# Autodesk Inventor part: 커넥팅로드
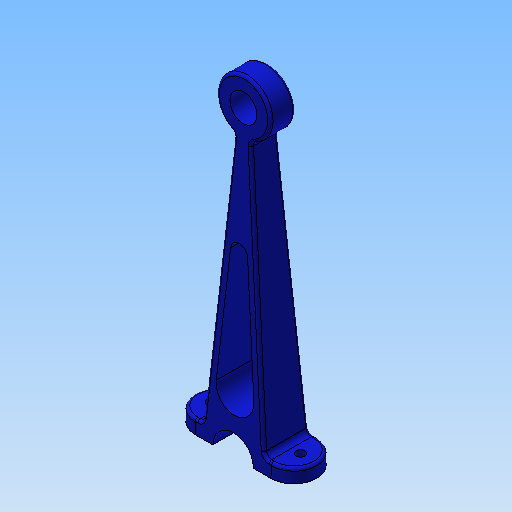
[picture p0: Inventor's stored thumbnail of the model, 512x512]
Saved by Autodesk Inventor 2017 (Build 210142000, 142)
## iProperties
Created: 2017-05
Part Number: 커넥팅로드
Material: 강철, 탄소
Document SubType Name: Modeling
Designer: mduedu
Density: 7.87 g/cm^3
Mass: 120.511 g
Surface Area: 85.3888 cm^2
Volume: 15.3127 cm^3
Appearance: 파란색 - 벽 페인트 - 무광
Author: mduedu
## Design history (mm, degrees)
sketch "스케치1"
  geometry: L1 (-22.5, 0)-(22.5, 0); L2 (22.5, 0)-(22.5, 5); L3 (-22.5, 5)-(-22.5, 0); L4 (-11.352, 5)-(-3, 100.461); L5 (0, 110)-(0, 0); L6 (11.352, 5)-(3, 100.461); L7 (22.5, 5)-(11.352, 5); L8 (-11.352, 5)-(-22.5, 5); C1 r 5 at (0, 110); A1 r 10 centre (0, 110) between (3, 100.461) and (-3, 100.461); 1 further point
  constraints: 16 end point, 4 parallel, 2 centre point, 2 coincident, 2 point on circle, 2 symmetric about line, 1 horizontal, 1 midpoint, 1 perpendicular, 1 vertical alignment
  dimensions: "d0" = 5 distance of L1.end L2.end; "d2" = 45 distance of L1.start L1.end; "d3" = 20 diameter of A1; "d4" = 10 diameter of C1; "d5" = 110 distance from line of L1 L5.start; "d6" = 5 deg angle of L5 L4; "d7" = 3 distance from line of L4.end L5
extrude "돌출1" new body sketch "스케치1" distance "d8" = 8.5; taper "d9" = 0 deg
sketch "스케치2"
  geometry: C1 r 7.5 at (0, 0); 1 further point
  constraints: 1 centre point, 1 coincident
  dimensions: "d10" = 15 diameter of C1
extrude "돌출2" cut sketch "스케치2" stored distance "d11" = 8.5; taper "d12" = 0 deg
sketch "스케치3"
  geometry: L1 (-3, 100.461)-(-11.352, 5) reference; L2 (11.352, 5)-(3, 100.461) reference; L3 (-3.154, 64.276)-(-6.975, 20.61); L4 (6.975, 20.61)-(3.154, 64.276); A1 r 3.166 centre (0, 64) between (3.154, 64.276) and (-3.154, 64.276); A2 r 7.001 centre (0, 20) between (-6.975, 20.61) and (6.975, 20.61); 1 further point
  constraints: 4 end point, 4 point on circle, 4 tangent, 2 centre point, 2 parallel, 1 vertical alignment
  dimensions: "d15" = 3 distance between parallel lines of L2 L4; "d16" = 44 distance of A2.centre A1.centre; "d17" = 20 distance of A2.centre point (0, 0)
extrude "돌출3" cut sketch "스케치3" stored distance "d18" = 8.5; taper "d19" = 0 deg
fillet "모깎기1" dims "d20" = 2
fillet "모깎기2" dims "d21" = 2
feature "면 기울기1" dims angle "d22" = 2 deg
fillet "모깎기3"
fillet "모깎기4"
fillet "모깎기5" dims "d28" = 1
sketch "스케치5"
  geometry: 3 further points
  constraints: 2 horizontal alignment
  dimensions: "d29" = 16.5 distance of point (-2.364, -7.36) point (14.136, -7.36); "d30" = 16.5 distance of point (30.636, -7.36) point (14.136, -7.36) (= d29)
sketch "스케치6"
  geometry: 2 further points
  constraints: 2 other
hole "구멍1" sketch "스케치6" at (-29.684, -7.36), (3.316, -7.36) diameter "d31" = 3.4; stored, may be unused: countersink angle "d35" = 90 deg, drill point angle "d37" = 0 deg; dims "d32" = 6, "d33" = 4, "d34" = 2, "d36" = 8
node "솔리드1"
mirror "대칭1"
other parameters: "d13" = 4, "d14" = 4
